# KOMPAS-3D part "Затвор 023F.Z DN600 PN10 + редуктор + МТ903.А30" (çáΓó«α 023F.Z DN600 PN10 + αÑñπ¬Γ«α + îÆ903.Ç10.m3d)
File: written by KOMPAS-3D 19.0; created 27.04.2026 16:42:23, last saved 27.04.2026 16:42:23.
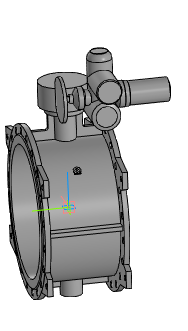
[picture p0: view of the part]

Document properties: Полное имя файла: ..\..\Затвор 023F.Z DN400-DN1600 + редуктор + МТ903\Затвор 023F.Z DN600 PN10 + редуктор + МТ903.А10.a3d

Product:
- Part/product: Затвор 023F.Z DN600 PN10 + редуктор + МТ903.А30
    Масса: 464.028

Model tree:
1. Операция без истории:1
